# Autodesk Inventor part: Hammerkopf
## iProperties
Created: 2005-12
Part Number: Hammerkopf
Document SubType Name: Modeling
Designer: Kumpf
Manufacturer: Standard
Standards Organization: Custom
Author: Kumpf
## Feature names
1. Drehung1 [Revolution]
2. Fase1 [Chamfer]
3. Bohrung1 [Hole]
4. Bohrung2 [Hole]
